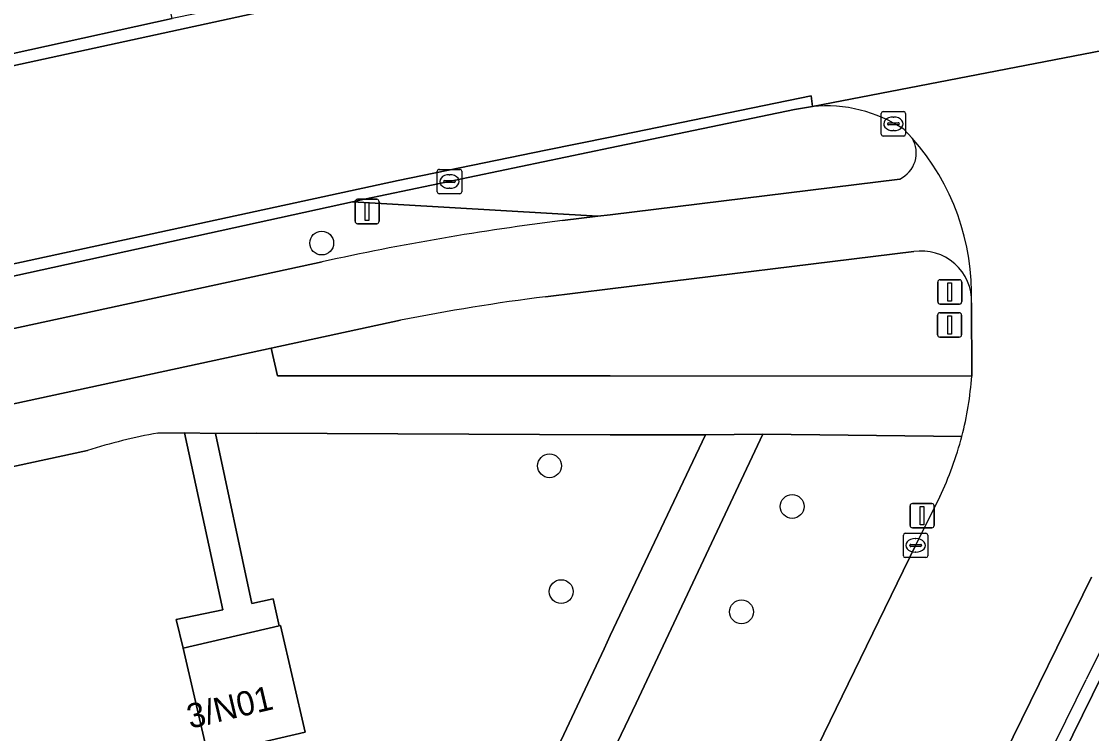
# Model space of a CAD drawing. Extents: x 160203 to 161530, y 379528 to 381797.
# Drawn here: x 160975.83 to 161019.76, y 380870.59 to 380899.83 of the extents above; entities that cross this region are included whole.
import ezdxf

# ---------------------------------------------------------------- set-up
doc = ezdxf.new("R2010")
doc.units = 0
for name, color, linetype in [('IMGEO_Berm_groen', 7, 'Continuous'), ('IMGEO_Boom', 7, 'Continuous'), ('IMGEO_Groenvoorziening', 7, 'Continuous'), ('IMGEO_Hek', 7, 'Continuous'), ('IMGEO_Kolk', 7, 'Continuous'), ('IMGEO_Lichtmast', 7, 'Continuous'), ('IMGEO_Loofbos', 7, 'Continuous'), ('IMGEO_Pand', 7, 'Continuous'), ('IMGEO_Pand_nummerreeks', 7, 'Continuous'), ('IMGEO_Rijbaan_lokaal_gesloten', 7, 'Continuous'), ('IMGEO_Rijbaan_lokaal_open', 7, 'Continuous'), ('IMGEO_Verkeersbordpaal', 7, 'Continuous'), ('IMGEO_Voetpad_open', 7, 'Continuous')]:
    doc.layers.add(name, color=color, linetype=linetype)

msp = doc.modelspace()

# ---------------------------------------------------------------- linework, layer by layer
at = {"layer": 'IMGEO_Berm_groen'}
for points in [[(161008.303, 380896.34), (161007.561, 380896.221), (161000, 380894.64), (160989.917, 380892.531), (160989.422, 380892.423), (160999.489, 380891.833), (161000, 380891.896), (161011.883, 380893.36)], [(161012.391, 380895.036), (161012.048, 380895.403)], [(160998.034, 380891.654), (160999.489, 380891.833), (160989.422, 380892.423), (160952.058, 380884.239), (160949.297, 380883.674), (160949.222, 380884.017), (160939.286, 380881.995), (160930.128, 380880.09), (160925.348, 380879.101), (160916.804, 380877.421), (160910.051, 380876.077), (160907.28, 380875.551), (160901.965, 380874.532), (160894.008, 380873.027), (160886.981, 380871.728), (160886.332, 380871.616), (160884.793, 380871.339), (160882.6, 380870.578), (160869.665, 380866.119), (160869.918, 380864.469), (160867.842, 380864.128), (160868.109, 380862.53), (160872.74, 380863.263)], [(161012.454, 380890.383), (161000, 380888.855), (160997.341, 380888.529)], [(160938.174, 380879.145), (160988.172, 380889.958)], [(160991.385, 380887.566), (160986.074, 380886.418), (160986.335, 380885.282), (161000, 380885.278), (161014.835, 380885.273), (161014.828, 380888.275)]]:
    msp.add_lwpolyline(points, dxfattribs=at)
for centre, radius, start, end in [((161008.851, 380890.58), 5.787, 56.4672, 95.4387), ((161011.376, 380894.429), 1.183, 295.3922, 30.8834), ((161010.818, 380787.794), 104.644, 97.01735, 102.49844), ((161012.766, 380888.343), 2.063, 358.1037, 98.6892), ((161008.563, 380800.221), 89.019, 97.2424, 101.12645)]:
    msp.add_arc(centre, radius, start, end, dxfattribs=at)
at = {"layer": 'IMGEO_Boom'}
for centre in [(160988.153, 380890.733), (160997.506, 380881.588), (161007.466, 380879.919), (160997.986, 380876.422), (161005.387, 380875.592)]:
    msp.add_circle(centre, 0.489, dxfattribs=at)
at = {"layer": 'IMGEO_Groenvoorziening'}
msp.add_lwpolyline([(161014.43, 380882.796), (161006.258, 380882.888), (161001.055, 380871.848), (161000, 380869.611), (160979.471, 380826.085), (160987.211, 380826.492), (161000, 380852.562), (161012.533, 380878.32), (161013.524, 380880.318)], dxfattribs=at)
msp.add_arc((161001.219, 380886.222), 13.648, 334.3699, 345.4635, dxfattribs=at)
at = {"layer": 'IMGEO_Hek'}
for points in [[(161021.256, 380876.29), (161019.536, 380872.814)], [(161000, 380833.086), (161019.536, 380872.814)]]:
    msp.add_lwpolyline(points, dxfattribs=at)
at = {"layer": 'IMGEO_Kolk'}
for p, q in [((161011.122, 380895.201), (161011.122, 380896.053)), ((161011.197, 380896.127), (161012.049, 380896.127)), ((161011.61, 380895.907), (161011.635, 380895.907)), ((161012.123, 380896.053), (161012.123, 380895.201)), ((161011.381, 380895.621), (161011.381, 380895.633)), ((161011.819, 380895.584), (161011.421, 380895.584)), ((161011.424, 380895.67), (161011.822, 380895.67)), ((161011.633, 380895.347), (161011.608, 380895.347)), ((161011.865, 380895.633), (161011.865, 380895.621)), ((161012.049, 380895.127), (161011.197, 380895.127)), ((160992.898, 380892.833), (160992.898, 380893.685)), ((160992.973, 380893.759), (160993.825, 380893.759)), ((160993.899, 380893.685), (160993.899, 380892.833)), ((160993.157, 380893.253), (160993.157, 380893.265)), ((160993.595, 380893.216), (160993.197, 380893.216)), ((160993.2, 380893.302), (160993.598, 380893.302)), ((160993.386, 380893.539), (160993.411, 380893.539)), ((160993.641, 380893.265), (160993.641, 380893.253)), ((160993.825, 380892.759), (160992.973, 380892.759)), ((160993.409, 380892.979), (160993.384, 380892.979)), ((161012.031, 380877.894), (161012.031, 380878.746)), ((161012.106, 380878.82), (161012.958, 380878.82)), ((161013.032, 380878.746), (161013.032, 380877.894)), ((161012.29, 380878.314), (161012.29, 380878.326)), ((161012.728, 380878.277), (161012.33, 380878.277)), ((161012.333, 380878.363), (161012.731, 380878.363)), ((161012.519, 380878.6), (161012.544, 380878.6)), ((161012.774, 380878.326), (161012.774, 380878.314)), ((161012.958, 380877.82), (161012.106, 380877.82)), ((161012.542, 380878.04), (161012.517, 380878.04))]:
    msp.add_line(p, q, dxfattribs=at)
for points in [[(161011.122, 380895.201), (161011.122, 380896.053)], [(161011.197, 380896.127), (161012.049, 380896.127)], [(161012.123, 380896.053), (161012.123, 380895.201)], [(161012.049, 380895.127), (161011.197, 380895.127)], [(160992.898, 380892.833), (160992.898, 380893.685)], [(160992.973, 380893.759), (160993.825, 380893.759)], [(160993.899, 380893.685), (160993.899, 380892.833)], [(160993.825, 380892.759), (160992.973, 380892.759)], [(161012.031, 380877.894), (161012.031, 380878.746)], [(161012.106, 380878.82), (161012.958, 380878.82)], [(161013.032, 380878.746), (161013.032, 380877.894)], [(161012.958, 380877.82), (161012.106, 380877.82)]]:
    msp.add_lwpolyline(points, dxfattribs=at)
for centre, radius, start, end in [((161011.199, 380896.051), 0.0765, 91.552, 178.448), ((161011.199, 380896.051), 0.0765, 91.552, 178.448), ((161012.047, 380896.051), 0.0765, 1.552, 88.448), ((161012.047, 380896.051), 0.0765, 1.552, 88.448), ((161011.421, 380895.63), 0.0403, 85.8775, 175.7526), ((161011.418, 380895.62), 0.0366, 178.938, 274.7102), ((161011.822, 380895.627), 0.043, 264.8664, 352.4533), ((161011.826, 380895.632), 0.0386, 1.7309, 96.639), ((161011.199, 380895.203), 0.0765, 181.552, 268.448), ((161011.199, 380895.203), 0.0765, 181.552, 268.448), ((161012.047, 380895.203), 0.0765, 271.552, 358.448), ((161012.047, 380895.203), 0.0765, 271.552, 358.448), ((160992.975, 380893.683), 0.0765, 91.552, 178.448), ((160992.975, 380893.683), 0.0765, 91.552, 178.448), ((160993.823, 380893.683), 0.0765, 1.552, 88.448), ((160993.823, 380893.683), 0.0765, 1.552, 88.448), ((160993.197, 380893.262), 0.0403, 85.8775, 175.7526), ((160993.194, 380893.252), 0.0366, 178.938, 274.7102), ((160993.598, 380893.259), 0.043, 264.8664, 352.4533), ((160993.602, 380893.264), 0.0386, 1.7309, 96.639), ((160992.975, 380892.835), 0.0765, 181.552, 268.448), ((160992.975, 380892.835), 0.0765, 181.552, 268.448), ((160993.823, 380892.835), 0.0765, 271.552, 358.448), ((160993.823, 380892.835), 0.0765, 271.552, 358.448), ((161012.108, 380878.744), 0.0765, 91.552, 178.448), ((161012.108, 380878.744), 0.0765, 91.552, 178.448), ((161012.956, 380878.744), 0.0765, 1.552, 88.448), ((161012.956, 380878.744), 0.0765, 1.552, 88.448), ((161012.33, 380878.323), 0.0403, 85.8775, 175.7526), ((161012.327, 380878.313), 0.0366, 178.938, 274.7102), ((161012.731, 380878.32), 0.043, 264.8664, 352.4533), ((161012.735, 380878.325), 0.0386, 1.7309, 96.639), ((161012.108, 380877.896), 0.0765, 181.552, 268.448), ((161012.108, 380877.896), 0.0765, 181.552, 268.448), ((161012.956, 380877.896), 0.0765, 271.552, 358.448), ((161012.956, 380877.896), 0.0765, 271.552, 358.448)]:
    msp.add_arc(centre, radius, start, end, dxfattribs=at)
for centre, major_axis, ratio, start_param, end_param in [((161011.609, 380895.627), (-0.387, 0.002), 0.722429, 4.712389, 7.853982), ((161011.634, 380895.627), (-0.39, 0.002), 0.717154, 1.570796, 4.712389), ((160993.385, 380893.259), (-0.387, 0.002), 0.722429, 4.712389, 7.853982), ((160993.41, 380893.259), (-0.39, 0.002), 0.717154, 1.570796, 4.712389), ((161012.518, 380878.32), (-0.387, 0.002), 0.722429, 4.712389, 7.853982), ((161012.543, 380878.32), (-0.39, 0.002), 0.717154, 1.570796, 4.712389)]:
    msp.add_ellipse(centre, major_axis=major_axis, ratio=ratio, start_param=start_param, end_param=end_param, dxfattribs=at)
at = {"layer": 'IMGEO_Lichtmast'}
for p, q in [((161012.304, 380879.14), (161012.304, 380879.94)), ((161012.304, 380879.94), (161012.304, 380879.14)), ((161012.404, 380880.04), (161013.194, 380880.04)), ((161013.194, 380880.04), (161012.404, 380880.04)), ((161013.294, 380879.94), (161013.294, 380879.14)), ((161013.294, 380879.14), (161013.294, 380879.94)), ((161013.194, 380879.04), (161012.404, 380879.04)), ((161012.404, 380879.04), (161013.194, 380879.04))]:
    msp.add_line(p, q, dxfattribs=at)
msp.add_lwpolyline([(161012.724, 380879.915), (161012.874, 380879.915), (161012.874, 380879.165), (161012.724, 380879.165), (161012.724, 380879.915)], dxfattribs=at)
for centre, start, end in [((161012.404, 380879.94), 90, 180), ((161012.404, 380879.94), 90, 180), ((161013.194, 380879.94), 0, 90), ((161013.194, 380879.94), 360, 90), ((161012.404, 380879.14), 180, 270), ((161012.404, 380879.14), 180, 270), ((161013.194, 380879.14), 270, 0), ((161013.194, 380879.14), 270, 0)]:
    msp.add_arc(centre, 0.1, start, end, dxfattribs=at)
at = {"layer": 'IMGEO_Loofbos'}
for points in [[(160988.453, 380850.065), (160999.745, 380874.075), (161000, 380874.614), (161003.901, 380882.863), (161000, 380882.861), (160985.481, 380882.929), (160983.794, 380882.914), (160985.288, 380875.939), (160986.155, 380876.131), (160986.401, 380875.015), (160986.46, 380875.029), (160987.48, 380870.655), (160983.483, 380869.723), (160982.463, 380874.096), (160982.181, 380875.275), (160984.101, 380875.679), (160982.526, 380882.935), (160981.427, 380882.933)], [(160978.543, 380882.221), (160939.893, 380873.87)]]:
    msp.add_lwpolyline(points, dxfattribs=at)
msp.add_arc((160985.937, 380858.47), 24.875, 100.4447, 107.291, dxfattribs=at)
at = {"layer": 'IMGEO_Pand'}
msp.add_lwpolyline([(160983.483, 380869.723), (160987.48, 380870.655), (160986.46, 380875.029), (160986.401, 380875.015), (160982.463, 380874.096)], close=True, dxfattribs=at)
at = {"layer": 'IMGEO_Rijbaan_lokaal_gesloten'}
for points in [[(160916.804, 380877.421), (160925.348, 380879.101), (160930.128, 380880.09), (160939.286, 380881.995), (160949.222, 380884.017), (160949.188, 380884.182), (160951.961, 380884.754), (160975.331, 380889.837), (160991.294, 380893.301), (160997.351, 380894.543), (161000, 380895.086), (161008.25, 380896.783), (161008.303, 380896.34), (161025.803, 380899.718), (161025.679, 380900.148), (161033.699, 380901.766), (161042.064, 380903.365), (161048.817, 380904.558), (161059.887, 380906.411), (161071.578, 380908.251)], [(161021.347, 380907.375), (161019.316, 380907.02), (161017.767, 380906.703), (161016.752, 380906.499), (161015.191, 380906.22), (161014.134, 380906.028), (161013.515, 380905.916), (161011.865, 380905.573), (161010.494, 380905.307), (161008.844, 380905.015), (161007.333, 380904.685), (161005.099, 380904.266), (161003.55, 380903.923), (161001.748, 380903.53), (161000, 380903.205), (160999.158, 380903.048), (160996.01, 380902.388), (160993.598, 380901.867), (160991.224, 380901.373), (160985.297, 380900.144), (160947.244, 380891.883)], [(161025.803, 380899.718), (161008.303, 380896.34)], [(161012.048, 380895.403), (161012.391, 380895.036)], [(161014.828, 380888.275), (161014.835, 380885.273)], [(161013.524, 380880.318), (161012.533, 380878.32), (161000, 380852.562), (160987.211, 380826.492), (160986.103, 380824.234), (160984.408, 380820.907)], [(160985.167, 380811.086), (160986.898, 380810.249), (160987.248, 380810.964), (160991.333, 380819.29), (160992.188, 380820.985), (161000, 380836.734), (161005.913, 380848.789), (161009.043, 380855.171), (161019.756, 380877.01)]]:
    msp.add_lwpolyline(points, dxfattribs=at)
msp.add_lwpolyline([(160949.222, 380884.017), (160949.297, 380883.674), (160952.058, 380884.239), (160989.422, 380892.423), (160989.917, 380892.531), (161000, 380894.64), (161007.561, 380896.221), (161008.303, 380896.34), (161008.25, 380896.783), (161000, 380895.086), (160997.351, 380894.543), (160991.294, 380893.301), (160975.331, 380889.837), (160951.961, 380884.754), (160949.188, 380884.182)], close=True, dxfattribs=at)
for centre, radius, start, end in [((161008.851, 380890.58), 5.787, 56.4672, 95.4387), ((161005.151, 380888.607), 9.683, 358.0371, 41.6062), ((161001.327, 380886.21), 13.541, 345.3963, 356.0319), ((161001.219, 380886.222), 13.648, 334.3699, 345.4635)]:
    msp.add_arc(centre, radius, start, end, dxfattribs=at)
at = {"layer": 'IMGEO_Rijbaan_lokaal_open'}
for points in [[(161070.931, 380916.755), (161057.972, 380914.74), (161047.916, 380913.066), (161036.668, 380910.98), (161035.245, 380910.712), (161026.971, 380909.153), (161014.063, 380906.647), (161007.879, 380905.407), (161000, 380903.805), (160988.094, 380901.385), (160986.136, 380900.802), (160982.013, 380899.947), (160964.472, 380896.088), (160960.833, 380895.342), (160954.002, 380893.819), (160938.378, 380890.521), (160922.193, 380887.127), (160906.72, 380884.039)], [(160947.244, 380891.883), (160985.297, 380900.144), (160991.224, 380901.373), (160993.598, 380901.867), (160996.01, 380902.388), (160999.158, 380903.048), (161000, 380903.205), (161001.748, 380903.53), (161003.55, 380903.923), (161005.099, 380904.266), (161007.333, 380904.685), (161008.844, 380905.015), (161010.494, 380905.307), (161011.865, 380905.573), (161013.515, 380905.916), (161014.134, 380906.028), (161015.191, 380906.22), (161016.752, 380906.499), (161017.767, 380906.703), (161019.316, 380907.02), (161021.347, 380907.375)], [(161011.883, 380893.36), (161000, 380891.896), (160999.489, 380891.833), (160998.034, 380891.654)], [(160997.341, 380888.529), (161000, 380888.855), (161012.454, 380890.383)], [(160988.172, 380889.958), (160938.174, 380879.145)], [(160938.74, 380876.184), (160986.074, 380886.418), (160991.385, 380887.566)], [(161168.832, 380845.637), (161168.832, 380851.085), (161181.899, 380851.085), (161181.899, 380858.079), (161169.414, 380857.943), (161169.414, 380863.195), (161169.414, 380864.082), (161169.414, 380869.951), (161190.574, 380869.951), (161190.893, 380876.912), (161024.332, 380876.912), (161024.332, 380881.333), (161024.208, 380881.179), (161010.548, 380853.369), (161008.225, 380848.64), (161000.089, 380832.075), (161050.739, 380832.156), (161050.659, 380826.754), (161049.884, 380826.754)]]:
    msp.add_lwpolyline(points, dxfattribs=at)
for centre, radius, start, end in [((161011.376, 380894.429), 1.183, 295.3922, 30.8834), ((161005.151, 380888.607), 9.683, 358.0371, 41.6062), ((161010.818, 380787.794), 104.644, 97.01735, 102.49844), ((161012.766, 380888.343), 2.063, 358.1037, 98.6892), ((161008.563, 380800.221), 89.019, 97.2424, 101.12645)]:
    msp.add_arc(centre, radius, start, end, dxfattribs=at)
at = {"layer": 'IMGEO_Verkeersbordpaal'}
for p, q in [((160989.522, 380891.628), (160989.522, 380892.428)), ((160989.522, 380892.428), (160989.522, 380891.628)), ((160989.622, 380892.528), (160990.412, 380892.528)), ((160990.412, 380892.528), (160989.622, 380892.528)), ((160990.512, 380892.428), (160990.512, 380891.628)), ((160990.512, 380891.628), (160990.512, 380892.428)), ((160990.412, 380891.528), (160989.622, 380891.528)), ((160989.622, 380891.528), (160990.412, 380891.528)), ((161013.54, 380889.228), (161014.33, 380889.228)), ((161014.33, 380889.228), (161013.54, 380889.228)), ((161013.44, 380888.328), (161013.44, 380889.128)), ((161013.44, 380889.128), (161013.44, 380888.328)), ((161014.43, 380889.128), (161014.43, 380888.328)), ((161014.43, 380888.328), (161014.43, 380889.128)), ((161013.531, 380887.869), (161014.321, 380887.869)), ((161014.321, 380887.869), (161013.531, 380887.869)), ((161014.33, 380888.228), (161013.54, 380888.228)), ((161013.54, 380888.228), (161014.33, 380888.228)), ((161013.431, 380886.969), (161013.431, 380887.769)), ((161013.431, 380887.769), (161013.431, 380886.969)), ((161014.421, 380887.769), (161014.421, 380886.969)), ((161014.421, 380886.969), (161014.421, 380887.769)), ((161014.321, 380886.869), (161013.531, 380886.869)), ((161013.531, 380886.869), (161014.321, 380886.869))]:
    msp.add_line(p, q, dxfattribs=at)
for points in [[(160989.942, 380892.403), (160990.092, 380892.403), (160990.092, 380891.653), (160989.942, 380891.653), (160989.942, 380892.403)], [(161013.86, 380889.103), (161014.01, 380889.103), (161014.01, 380888.353), (161013.86, 380888.353), (161013.86, 380889.103)], [(161013.851, 380887.744), (161014.001, 380887.744), (161014.001, 380886.994), (161013.851, 380886.994), (161013.851, 380887.744)]]:
    msp.add_lwpolyline(points, dxfattribs=at)
for centre, start, end in [((160989.622, 380892.428), 90, 180), ((160989.622, 380892.428), 90, 180), ((160990.412, 380892.428), 0, 90), ((160990.412, 380892.428), 360, 90), ((160989.622, 380891.628), 180, 270), ((160989.622, 380891.628), 180, 270), ((160990.412, 380891.628), 270, 0), ((160990.412, 380891.628), 270, 0), ((161013.54, 380889.128), 90, 180), ((161013.54, 380889.128), 90, 180), ((161014.33, 380889.128), 0, 90), ((161014.33, 380889.128), 360, 90), ((161013.54, 380888.328), 180, 270), ((161013.54, 380888.328), 180, 270), ((161014.33, 380888.328), 270, 0), ((161014.33, 380888.328), 270, 0), ((161013.531, 380887.769), 90, 180), ((161013.531, 380887.769), 90, 180), ((161014.321, 380887.769), 0, 90), ((161014.321, 380887.769), 360, 90), ((161013.531, 380886.969), 180, 270), ((161013.531, 380886.969), 180, 270), ((161014.321, 380886.969), 270, 0), ((161014.321, 380886.969), 270, 0)]:
    msp.add_arc(centre, 0.1, start, end, dxfattribs=at)
at = {"layer": 'IMGEO_Voetpad_open'}
for points in [[(160981.227, 380903.464), (160969.195, 380900.858), (160968.183, 380905.66), (160967.008, 380905.21), (160968.125, 380900.122), (160963.79, 380899.159), (160964.472, 380896.088), (160982.013, 380899.947)], [(161000, 380869.611), (161001.055, 380871.848), (161006.258, 380882.888), (161003.901, 380882.863), (161000, 380874.614), (160999.745, 380874.075), (160988.453, 380850.065), (160976.105, 380823.809), (160986.103, 380824.234), (160987.211, 380826.492), (160979.471, 380826.085)], [(160986.401, 380875.015), (160986.155, 380876.131), (160985.288, 380875.939), (160983.794, 380882.914), (160982.526, 380882.935), (160984.101, 380875.679), (160982.181, 380875.275), (160982.463, 380874.096)]]:
    msp.add_lwpolyline(points, close=True, dxfattribs=at)
for points in [[(161014.835, 380885.273), (161000, 380885.278), (160986.335, 380885.282), (160986.074, 380886.418), (160938.74, 380876.184)], [(160981.427, 380882.933), (160982.526, 380882.935), (160983.794, 380882.914), (160985.481, 380882.929), (161000, 380882.861), (161003.901, 380882.863), (161006.258, 380882.888), (161014.43, 380882.796)], [(160939.893, 380873.87), (160978.543, 380882.221)], [(161019.756, 380877.01), (161009.043, 380855.171), (161010.187, 380853.802), (161010.548, 380853.369), (161024.208, 380881.179)]]:
    msp.add_lwpolyline(points, dxfattribs=at)
for centre, radius, start, end in [((161001.327, 380886.21), 13.541, 345.3963, 356.0319), ((160985.937, 380858.47), 24.875, 100.4447, 107.291)]:
    msp.add_arc(centre, radius, start, end, dxfattribs=at)

# ---------------------------------------------------------------- texts
at = {"layer": 'IMGEO_Pand_nummerreeks'}
msp.add_text('3/N01', height=1, rotation=13.2609, dxfattribs=at).set_placement((160982.754, 380870.788))

doc.saveas('drawing.dxf')
